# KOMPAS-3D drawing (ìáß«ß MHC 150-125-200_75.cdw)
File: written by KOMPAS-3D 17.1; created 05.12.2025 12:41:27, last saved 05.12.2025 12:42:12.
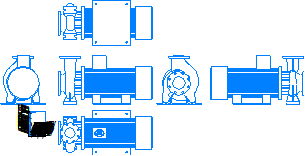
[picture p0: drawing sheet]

Sheet 1: A4, portrait

Title block, sheet 1: name: Насос MHC 150-125-200_75 / 75 кВт 3х380В; material: Сталь 10  ГОСТ 1050-88; mass: 842,83; sheets: 1; sheet format: A4

Views: Вид 1, Спереди, Проекционный вид 2, Проекционный вид 3, Проекционный вид 4, Проекционный вид 5, Проекционный вид 6
Referenced files in \\adlc.lan\data\АДЛ_ПКД\3D-модели\ADL production\Насосы ГРАНПАМП\Насосы ГРАНПАМП серии МНС\KOMPAS 3D\: Насос MHC 150-125-200_75.m3d
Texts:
  Andrey
  АДЛ
Dimensions and other numbers on the sheet: 1:1; 1; 75 кВт 3х380В; 842,83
